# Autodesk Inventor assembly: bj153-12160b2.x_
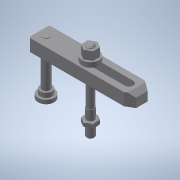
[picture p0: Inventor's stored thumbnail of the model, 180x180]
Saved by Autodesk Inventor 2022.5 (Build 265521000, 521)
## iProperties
Part Number: bj153-12160b2.x_
Material: 一般
Document SubType Name: Assembly
Designer: ImaoCorp
Sending System: SOLIDWORKS 2017-2017317
MC: AMD64
MC_MODEL: Intel64 Family 6 Model 60 Stepping 3, GenuineIntel
OS: Windows_NT
FRU: Parasolid Version 29.0, build 201,  4-17-2017
FORMAT: text
GUISE: transmit
KEY: bj153-12160b2
FILE: bj153-12160b2.x_t
DATE: Fri Mar 15 10:24:20 2019
Author: ImaoCorp
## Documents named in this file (6)
- X:\14_SW2022-Inv2022\00_全2023-1023新製品(TCC)まで\b\bj153-12160b2\BJ153-12160B2.iam
- X:\14_SW2022-Inv2022\00_全2023-1023新製品(TCC)まで\b\bj153-12160b2\bj153-12160b2_01.ipt
- X:\14_SW2022-Inv2022\00_全2023-1023新製品(TCC)まで\b\bj153-12160b2\bj153-12160b2_02.ipt
- X:\14_SW2022-Inv2022\00_全2023-1023新製品(TCC)まで\b\bj153-12160b2\bj153-12160b2_03.ipt
- X:\14_SW2022-Inv2022\00_全2023-1023新製品(TCC)まで\b\bj153-12160b2\bj153-12160b2_04.ipt
- X:\14_SW2022-Inv2022\00_全2023-1023新製品(TCC)まで\b\bj153-12160b2\bj153-12160b2_05.ipt
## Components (5 placed, 5 different names)
1. bj153-12160b2_01
2. bj153-12160b2_02
3. bj153-12160b2_03
4. bj153-12160b2_04
5. bj153-12160b2_05
